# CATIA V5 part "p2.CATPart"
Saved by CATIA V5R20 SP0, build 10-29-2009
Part number: p2
Publications: "Line.10", "Line.11", "Line.12", "Line.13", "Line.14", "Line.15", "Plane.2"
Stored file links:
  D:\Dropbox\IAO_2011\MMS_GR2\IAO_2011_1439_jlicbarski\p2.CATPart
  D:\Dropbox\IAO_2011\MMS_GR2\IAO_2011_1439_jlicbarski\train.CATProduct

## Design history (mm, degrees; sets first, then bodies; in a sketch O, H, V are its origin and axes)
AxisSystem1: origin (0, 0, 0), X (1, 0, 0), Y (0, 1, 0), Z (0, 0, 1)
Set1
  Point1: linked copy from another document
  Point2: linked copy from another document
  Plane1: linked copy from another document
  Point3: linked copy from another document
Body1 (main body)
  Line1: type PtDir, RefPoint Point1, Direction edge [XY plane of AxisSystem1 | ZX plane of AxisSystem1], Start 0, End -30
  Line2: type PtDir, RefPoint Point2, Direction edge [XY plane of AxisSystem1 | ZX plane of AxisSystem1], Start 0, End -30
  Line3: type PtPt, FirstPoint vertex of Line2, SecondPoint vertex of Line1
  Plane2: type Normal, Curve Line1
  Line4: type PtDir, RefPoint Point3, Direction edge [XY plane of AxisSystem1 | ZX plane of AxisSystem1], Start 0, End -17.5
  Line5: type PtPt, FirstPoint vertex of Line4, SecondPoint vertex of Line2
  Line6: type PtPt, FirstPoint vertex of Line4, SecondPoint vertex of Line1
